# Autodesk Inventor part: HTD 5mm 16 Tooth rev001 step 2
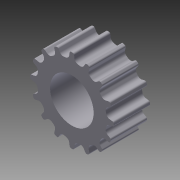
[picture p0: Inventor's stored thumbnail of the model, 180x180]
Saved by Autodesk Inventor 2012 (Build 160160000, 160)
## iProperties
Created: 2011-12
Part Number: HTD 5mm 16 Tooth rev001 step 2
Document SubType Name: Modeling
Designer: Alex
Density: 2.71 g/cm^3
Material: Aluminum-6061
Mass: 7.10726 g
Surface Area: 20.6477 cm^2
Volume: 2.62261 cm^3
Author: Alex
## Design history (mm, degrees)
sketch "Sketch2"
  geometry: C1 r 12.167 at (0, 0); 1 further point
  constraints: 1 centre point, 1 coincident
  dimensions: "d161" = 24.3332 diameter of C1
extrude "Extrusion1" new body sketch "Sketch2" distance "d162" = 10.5664; taper "d163" = 0 deg
sketch "Sketch1"
  geometry: L1 (-28.232, 0)-(27.326, 0); L2 (1.678, 9.999)-(2.276, 9.88); L3 (0.656, 11.771)-(0.769, 10.962); L4 (3.899, 11.126)-(3.484, 10.422); L5 (-12.145, 12.188)-(12.188, 12.145); L6 (12.188, 12.145)-(12.145, -12.188); L7 (12.145, -12.188)-(-12.188, -12.145); L8 (-12.188, -12.145)-(-12.145, 12.188); L9 (-3.899, 11.126)-(-3.484, 10.422); L10 (-2.276, 9.88)-(-1.678, 9.999); L11 (-0.656, 11.771)-(-0.769, 10.962); L12 (-7.86, 8.787)-(-7.207, 8.295); L13 (-5.884, 8.257)-(-5.377, 8.596); L14 (-5.111, 10.624)-(-4.906, 9.833); L15 (-10.624, 5.111)-(-9.833, 4.906); L16 (-8.596, 5.377)-(-8.257, 5.884); L17 (-8.787, 7.86)-(-8.295, 7.207); L18 (-11.771, 0.656)-(-10.962, 0.769); L19 (-9.999, 1.678)-(-9.88, 2.276); L20 (-11.126, 3.899)-(-10.422, 3.484); L21 (-11.126, -3.899)-(-10.422, -3.484); L22 (-9.88, -2.276)-(-9.999, -1.678); L23 (-11.771, -0.656)-(-10.962, -0.769); L24 (-8.787, -7.86)-(-8.295, -7.207); L25 (-8.257, -5.884)-(-8.596, -5.377); L26 (-10.624, -5.111)-(-9.833, -4.906); L27 (-5.111, -10.624)-(-4.906, -9.833); L28 (-5.377, -8.596)-(-5.884, -8.257); L29 (-7.86, -8.787)-(-7.207, -8.295); L30 (-0.656, -11.771)-(-0.769, -10.962); L31 (-1.678, -9.999)-(-2.276, -9.88); L32 (-3.899, -11.126)-(-3.484, -10.422); L33 (3.899, -11.126)-(3.484, -10.422); L34 (2.276, -9.88)-(1.678, -9.999); L35 (0.656, -11.771)-(0.769, -10.962); L36 (7.86, -8.787)-(7.207, -8.295); L37 (5.884, -8.257)-(5.377, -8.596); L38 (5.111, -10.624)-(4.906, -9.833); L39 (10.624, -5.111)-(9.833, -4.906); L40 (8.596, -5.377)-(8.257, -5.884); L41 (8.787, -7.86)-(8.295, -7.207); L42 (11.771, -0.656)-(10.962, -0.769); L43 (9.999, -1.678)-(9.88, -2.276); L44 (11.126, -3.899)-(10.422, -3.484); L45 (11.126, 3.899)-(10.422, 3.484); L46 (9.88, 2.276)-(9.999, 1.678); L47 (11.771, 0.656)-(10.962, 0.769); L48 (8.787, 7.86)-(8.295, 7.207); L49 (8.257, 5.884)-(8.596, 5.377); L50 (10.624, 5.111)-(9.833, 4.906); L51 (5.111, 10.624)-(4.906, 9.833); L52 (5.377, 8.596)-(5.884, 8.257); L53 (7.86, 8.787)-(7.207, 8.295); A1 r 0.457 centre (0.203, 11.708) between (0.656, 11.771) and (0.211, 12.165); A2 r 0.457 centre (4.293, 10.894) between (4.46, 11.32) and (3.899, 11.126); A3 r 1.143 centre (2.499, 11.001) between (2.276, 9.88) and (3.484, 10.422); A4 r 1.143 centre (1.901, 11.12) between (0.769, 10.962) and (1.678, 9.999); A5 r 12.167 centre (0, 0) between (4.46, 11.32) and (0.211, 12.165); A6 r 12.167 centre (0, 0) between (-12.167, 0.021) and (-12.167, 0); A7 r 12.167 centre (0, 0) between (12.167, -0.021) and (12.167, 0); A8 r 0.457 centre (-4.293, 10.894) between (-3.899, 11.126) and (-4.46, 11.32); A9 r 1.143 centre (-2.499, 11.001) between (-3.484, 10.422) and (-2.276, 9.88); A10 r 1.143 centre (-1.901, 11.12) between (-1.678, 9.999) and (-0.769, 10.962); A11 r 0.457 centre (-0.203, 11.708) between (-0.211, 12.165) and (-0.656, 11.771); A12 r 12.167 centre (0, 0) between (-0.211, 12.165) and (-4.46, 11.32); A13 r 0.457 centre (-8.135, 8.422) between (-7.86, 8.787) and (-8.452, 8.751); A14 r 1.143 centre (-6.519, 9.208) between (-7.207, 8.295) and (-5.884, 8.257); A15 r 1.143 centre (-6.012, 9.546) between (-5.377, 8.596) and (-4.906, 9.833); A16 r 0.457 centre (-4.668, 10.739) between (-4.85, 11.158) and (-5.111, 10.624); A17 r 12.167 centre (0, 0) between (-4.85, 11.158) and (-8.452, 8.751); A18 r 0.457 centre (-10.739, 4.668) between (-10.624, 5.111) and (-11.158, 4.85); A19 r 1.143 centre (-9.546, 6.012) between (-9.833, 4.906) and (-8.596, 5.377); A20 r 1.143 centre (-9.208, 6.519) between (-8.257, 5.884) and (-8.295, 7.207); A21 r 0.457 centre (-8.422, 8.135) between (-8.751, 8.452) and (-8.787, 7.86); A22 r 12.167 centre (0, 0) between (-8.751, 8.452) and (-11.158, 4.85); A23 r 0.457 centre (-11.708, 0.203) between (-11.771, 0.656) and (-12.165, 0.211); A24 r 1.143 centre (-11.12, 1.901) between (-10.962, 0.769) and (-9.999, 1.678); A25 r 1.143 centre (-11.001, 2.499) between (-9.88, 2.276) and (-10.422, 3.484); A26 r 0.457 centre (-10.894, 4.293) between (-11.32, 4.46) and (-11.126, 3.899); A27 r 12.167 centre (0, 0) between (-11.32, 4.46) and (-12.165, 0.211); A28 r 0.457 centre (-10.894, -4.293) between (-11.126, -3.899) and (-11.32, -4.46); A29 r 1.143 centre (-11.001, -2.499) between (-10.422, -3.484) and (-9.88, -2.276); A30 r 1.143 centre (-11.12, -1.901) between (-9.999, -1.678) and (-10.962, -0.769); A31 r 0.457 centre (-11.708, -0.203) between (-12.165, -0.211) and (-11.771, -0.656); A32 r 12.167 centre (0, 0) between (-12.165, -0.211) and (-11.32, -4.46); A33 r 0.457 centre (-8.422, -8.135) between (-8.787, -7.86) and (-8.751, -8.452); A34 r 1.143 centre (-9.208, -6.519) between (-8.295, -7.207) and (-8.257, -5.884); A35 r 1.143 centre (-9.546, -6.012) between (-8.596, -5.377) and (-9.833, -4.906); A36 r 0.457 centre (-10.739, -4.668) between (-11.158, -4.85) and (-10.624, -5.111); A37 r 12.167 centre (0, 0) between (-11.158, -4.85) and (-8.751, -8.452); A38 r 0.457 centre (-4.668, -10.739) between (-5.111, -10.624) and (-4.85, -11.158); A39 r 1.143 centre (-6.012, -9.546) between (-4.906, -9.833) and (-5.377, -8.596); A40 r 1.143 centre (-6.519, -9.208) between (-5.884, -8.257) and (-7.207, -8.295); A41 r 0.457 centre (-8.135, -8.422) between (-8.452, -8.751) and (-7.86, -8.787); A42 r 12.167 centre (0, 0) between (-8.452, -8.751) and (-4.85, -11.158); A43 r 0.457 centre (-0.203, -11.708) between (-0.656, -11.771) and (-0.211, -12.165); A44 r 1.143 centre (-1.901, -11.12) between (-0.769, -10.962) and (-1.678, -9.999); A45 r 1.143 centre (-2.499, -11.001) between (-2.276, -9.88) and (-3.484, -10.422); A46 r 0.457 centre (-4.293, -10.894) between (-4.46, -11.32) and (-3.899, -11.126); A47 r 12.167 centre (0, 0) between (-4.46, -11.32) and (-0.211, -12.165); A48 r 0.457 centre (4.293, -10.894) between (3.899, -11.126) and (4.46, -11.32); A49 r 1.143 centre (2.499, -11.001) between (3.484, -10.422) and (2.276, -9.88); A50 r 1.143 centre (1.901, -11.12) between (1.678, -9.999) and (0.769, -10.962); A51 r 0.457 centre (0.203, -11.708) between (0.211, -12.165) and (0.656, -11.771); A52 r 12.167 centre (0, 0) between (0.211, -12.165) and (4.46, -11.32); A53 r 0.457 centre (8.135, -8.422) between (7.86, -8.787) and (8.452, -8.751); A54 r 1.143 centre (6.519, -9.208) between (7.207, -8.295) and (5.884, -8.257); A55 r 1.143 centre (6.012, -9.546) between (5.377, -8.596) and (4.906, -9.833); A56 r 0.457 centre (4.668, -10.739) between (4.85, -11.158) and (5.111, -10.624); A57 r 12.167 centre (0, 0) between (4.85, -11.158) and (8.452, -8.751); A58 r 0.457 centre (10.739, -4.668) between (10.624, -5.111) and (11.158, -4.85); A59 r 1.143 centre (9.546, -6.012) between (9.833, -4.906) and (8.596, -5.377); A60 r 1.143 centre (9.208, -6.519) between (8.257, -5.884) and (8.295, -7.207); A61 r 0.457 centre (8.422, -8.135) between (8.751, -8.452) and (8.787, -7.86); A62 r 12.167 centre (0, 0) between (8.751, -8.452) and (11.158, -4.85); A63 r 0.457 centre (11.708, -0.203) between (11.771, -0.656) and (12.165, -0.211); A64 r 1.143 centre (11.12, -1.901) between (10.962, -0.769) and (9.999, -1.678)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; 1 further point; 1 other entity
  constraints: 164 point on circle, 98 end point, 82 centre point, 3 point on line, 3 tangent, 2 midpoint, 1 coincident, 339 other
  dimensions: "d130" = 12.1666 distance from line of point (0, 0) L8; "d131" = 12.1666 distance from line of point (0, 0) L5; "d132" = 89.9 deg angle of L8 L1; "d145" = 24.3332 distance between parallel lines of L7 L5; "d185" = 360 deg dimension on point (0, 0) A1.centre (derived)
extrude "Extrusion2" cut sketch "Sketch1" stored distance "d202" = 0; taper "d203" = 0 deg
sketch "Sketch3"
  geometry: C1 r 6.35 at (0, 0); A1 r 12.167 centre (0, 0) between (-4.46, 11.32) and (-4.85, 11.158) reference
  constraints: 1 centre point, 1 coincident
  dimensions: "d204" = 12.7 diameter of C1
extrude "Extrusion3" cut sketch "Sketch3" stored distance "d205" = 10.5664; taper "d206" = 0 deg
body "Solid1"
node "Image3"
other parameters: "d0" = 24.3332, "d46" = 2.032, "d47" = 2.286
